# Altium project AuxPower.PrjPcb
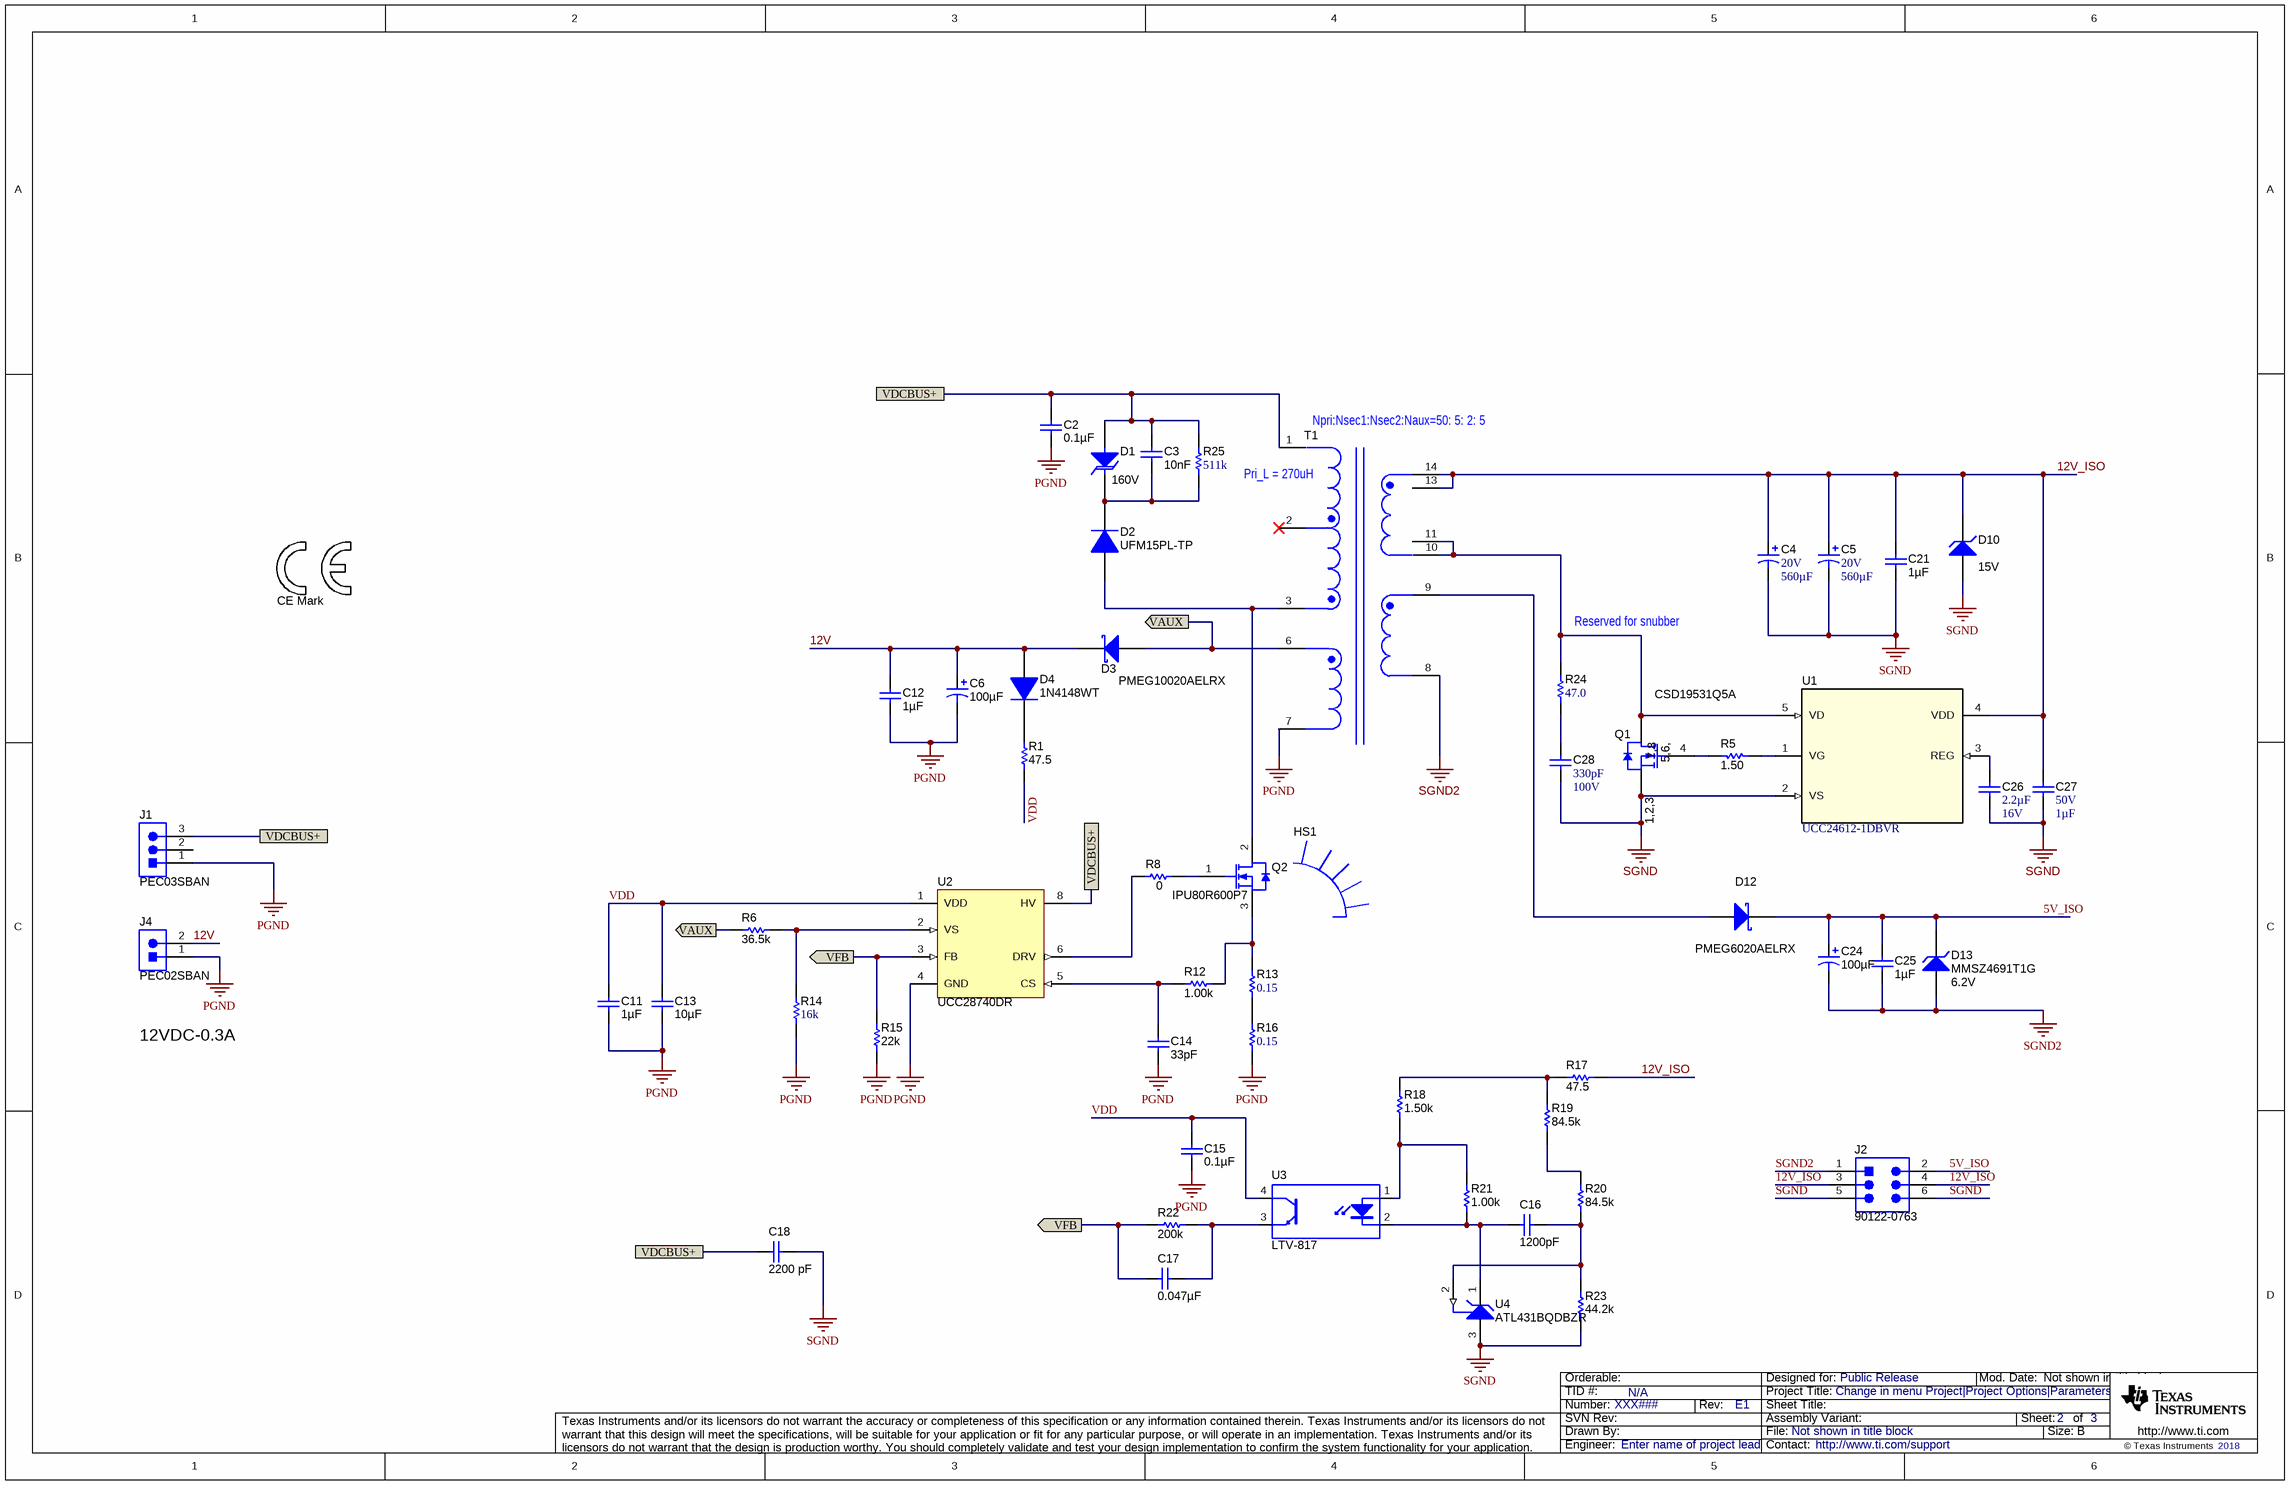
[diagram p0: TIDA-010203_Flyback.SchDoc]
CopyrightYear: 2018; PCB_Layout: Who did the Layout?; PCB_Rev: E1; PRJ_Customer: Public Release; PRJ_Engineer: Enter name of project lead; PRJ_Number: XXX###; PRJ_Title: Change in menu Project|Project Options|Parameters; SCH_Rev: E1; TechSupport: http://www.ti.com/support; TID: N/A
1 sheet, 56 parts. Net scope: flat (ports and power ports of the same name join across sheets).
Board file: TIDA-010203_Flyback.PcbDoc

## Sheet TIDA-010203_Flyback.SchDoc
size 431 x 279 mm; Date: Not shown in title block; ApprovedBy: Not shown in title block; CheckedBy: Not shown in title block; Author: Not shown in title block; CompanyName: Not shown in title block; Engineer: Not shown in title block; Organization: Not shown in title block; Address1: Not shown in title block; Address2: Not shown in title block; Address3: Not shown in title block; Address4: Not shown in title block; DocumentNumber: 1; Revision: Use project parameter SCH_Rev; SheetNumber: 2; SheetTotal: 3; PageSetup: Record=PageOptions¦CenterHorizontal=True¦CenterVertical=True¦PrintScale=1.00¦XCorrection=1.00¦YCorrection=1.00¦PrintKind=0¦BorderSize=5000000¦LeftOffset=0¦BottomOffset=0¦Orientation=2¦PaperLength=1000¦PaperWidth=1000¦Scale=100¦PaperSource=15¦PrintQuality=600¦MediaType=1¦DitherType=10¦PaperKind=Letter¦PrintScaleMode=1

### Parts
C2  ValueDisplayed: 0.1µF  [WCAP-FTXX_P10PL20_13x5x11]  (hidden comment: B32671P6104K)
C3  ValueDisplayed: 10nF  [0805_HV]  (hidden comment: C0805W103KBRAC7800)
C4  VDC_V: 20V  ValueDisplayed: 560µF  [SEPF_F13]  (hidden comment: 20SEPF560M)
C5  VDC_V: 20V  ValueDisplayed: 560µF  [SEPF_F13]  (hidden comment: 20SEPF560M)
C6  ValueDisplayed: 100µF  [CAPPR2-5x11]  (hidden comment: 25YXJ100M5X11)
C11  ValueDisplayed: 1µF  [0603]  (hidden comment: GRM188R61E105KA12D)
C12  ValueDisplayed: 1µF  [0603]  (hidden comment: C0603C105K3RACTU)
C13  ValueDisplayed: 10µF  [0603]  (hidden comment: GRM188R61E106MA73D)
C14  ValueDisplayed: 33pF  [0603]  (hidden comment: GRM1885C1H330JA01D)
C15  ValueDisplayed: 0.1µF  [0603]  (hidden comment: C1608X7R1H104K)
C16  ValueDisplayed: 1200pF  [0603]  (hidden comment: C1608C0G1H122J)
C17  ValueDisplayed: 0.047µF  [0603]  (hidden comment: C1608X7R1H473K)
C18  ValueDisplayed: 2200 pF  [C921_5500T_VertKink]  (hidden comment: DE1E3KX222MN4AP01F)
C21  ValueDisplayed: 1µF  [0603]  (hidden comment: C0603C105K3RACTU)
C24  ValueDisplayed: 100µF  [CAPPR2-5x11]  (hidden comment: 25YXJ100M5X11)
C25  ValueDisplayed: 1µF  [0603]  (hidden comment: C0603C105K3RACTU)
C26  Cap_F: 2.2µF  VDC_V: 16V  [0805_HV]  (hidden comment: GRM219R71C225KE15)
C27  VDC_V: 50V  Cap_F: 1µF  [0805_HV]  (hidden comment: GJ821BR71H105KA12L)
C28  Cap_F: 330pF  VDC_V: 100V  [0805_HV]  (hidden comment: 08051C331KAT2A)
D1  value 160V  [SMB]  (hidden comment: SMBJ160A)
D2  UFM15PL-TP  [SOD-123FL]
D3  PMEG10020AELRX  [SOD-123FL]
D4  1N4148WT  [Fairchild_SOD-523F]
D10  value 15V  [SOD-123]  (hidden comment: BZT52C15-7-F)
D12  PMEG6020AELRX  [SOD-123]
D13  MMSZ4691T1G  value 6.2V  [SOD-123]
HS1  ATS-PCBT1093  [HS_ATS-PCB1093]  (value not drawn)
J1  PEC03SBAN  [Sullins_PEC03SBAN]
J2  90122-0763  [Molex_90122-0763]
J4  PEC02SBAN  [Sullins_xxC02SBAN]
Logo8  CE Mark  [CE_Mark_5mm]  (no BOM)
Q1  CSD19531Q5A  [TRANS_NexFET_Q5A]
Q2  IPU80R600P7  [IPAK]
R1  ValueDisplayed: 47.5  [0805_HV]  (hidden comment: CRCW080547R5FKEA)
R5  ValueDisplayed: 1.50  [0603]  (hidden comment: CRCW06031R50FKEA)
R6  ValueDisplayed: 36.5k  [0603]  (hidden comment: CRCW060336K5FKEA)
R8  ValueDisplayed: 0  [0603]  (hidden comment: CRCW06030000Z0EA)
R12  ValueDisplayed: 1.00k  [0603]  (hidden comment: CRCW06031K00FKEA)
R13  ValueDisplayed: 0.15  [1206]  (hidden comment: ERJ-8BSFR15V)
R14  ValueDisplayed: 16k  [0603]  (hidden comment: 16k 0603)
R15  ValueDisplayed: 22k  [0603]  (hidden comment: CRCW060322K0JNEA)
R16  ValueDisplayed: 0.15  [1206]  (hidden comment: ERJ-8BSFR15V)
R17  ValueDisplayed: 47.5  [0603]  (hidden comment: CRCW060347R5FKEA)
R18  ValueDisplayed: 1.50k  [0603]  (hidden comment: CRCW06031K50FKEA)
R19  ValueDisplayed: 84.5k  [0603]  (hidden comment: CRCW060384K5FKEA)
R20  ValueDisplayed: 84.5k  [0603]  (hidden comment: CRCW060384K5FKEA)
R21  ValueDisplayed: 1.00k  [0603]  (hidden comment: CRCW06031K00FKEA)
R22  ValueDisplayed: 200k  [0603]  (hidden comment: CRCW0603200KFKEA)
R23  ValueDisplayed: 44.2k  [0603]  (hidden comment: CRCW060344K2FKEA)
R24  ValueDisplayed: 47.0  [0805_HV]  (hidden comment: MCU08050C4709FP500)
R25  ValueDisplayed: 511k  [1210]  (hidden comment: RC1210FR-07511KL)
T1  750344721  [WE_25/13/7]  (value not drawn)
U1  UCC24612-1DBVR  [DBV0005A_N]
U2  UCC28740DR  [D0007A_N]
U3  LTV-817  [DIP762W60P254L460H350Q4B]
U4  ATL431BQDBZR  [DBZ0003A_N]

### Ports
VAUX (out), VDCBUS+, VFB (out)

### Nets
PGND: C2.2 C6.2(-) C11.2 C12.2 C13.2 C14.2 C15.2 J1.1 J4.1 R14.1 R15.1 R16.1 T1.7 U2.4(GND)
SGND: C4.2(-) C5.2(-) C18.1 C21.2 C26.2 C27.2 C28.2 D10.2(A) J2.5 J2.6 Q1.1(S) Q1.2(S) Q1.3(S) R23.2 U1.2(VS) U4.3(ANODE)
SGND2: C24.2(-) C25.2 D13.2(A) J2.1 T1.8
5V_ISO: C24.1(+) C25.1 D12.1(K) D13.1(K) J2.2
12V: C6.1(+) C12.1 D3.1(K) D4.2(A) J4.2
12V_ISO: C4.1(+) C5.1(+) C21.1 C27.1 D10.1(K) J2.3 J2.4 R17.1 T1.13 T1.14 U1.4(VDD)
VAUX: D3.2(A) R6.2 T1.6 ; port VAUX
VDCBUS+: C2.1 C3.1 C18.2 D1.2(A) J1.3 R25.2 T1.1 U2.8(HV) ; port VDCBUS+
VDD: C11.1 C13.1 C15.1 R1.2 U2.1(VDD) U3.4(C)
VFB: C17.1 R15.2 R22.1 U2.3(FB) ; port VFB
NetC3_2: C3.2 D1.1(K) D2.1(K) R25.1
NetC14_1: C14.1 R12.1 U2.5(CS)
NetC16_1: C16.1 R20.1 R23.1 U4.2(REF)
NetC16_2: C16.2 R21.1 U3.2(K) U4.1(CATHODE)
NetC17_2: C17.2 R22.2 U3.3(E)
NetC26_1: C26.1 U1.3(REG)
NetC28_1: C28.1 R24.1
NetD2_2: D2.2(A) Q2.2(D) T1.3
NetD4_1: D4.1(K) R1.1
NetD12_2: D12.2(A) T1.9
NetQ1_4: Q1.4(G) R5.2
NetQ1_5: Q1.5(D) Q1.6(D) Q1.7(D) Q1.8(D) Q1.9(D) R24.2 T1.10 T1.11 U1.5(VD)
NetQ2_1: Q2.1(G) R8.2
NetQ2_3: Q2.3(S) R12.2 R13.2
NetR5_1: R5.1 U1.1(VG)
NetR6_1: R6.1 R14.2 U2.2(VS)
NetR8_1: R8.1 U2.6(DRV)
NetR13_1: R13.1 R16.2
NetR17_2: R17.2 R18.1 R19.2
NetR18_2: R18.2 R21.2 U3.1(A)
NetR19_1: R19.1 R20.2

Not connected (* = marked no-connect by the designer): J1 2; T1 2*

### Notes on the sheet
- (near T1) Npri:Nsec1:Nsec2:Naux=50: 5: 2: 5
- (near T1) Pri_L = 270uH
- (near R24) Reserved for snubber
- 12VDC-0.3A

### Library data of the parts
C2 = 890334023006: CAP, Film, 0.1 µF, 630 V, +/- 10%, TH; Manufacturer: TDK; Polarized: N; CompType: Capacitor; Value: 0.1uF; U/M: EA; Cap_F: 0.00000001; Tolerance_%: 10; Value1: Unknown; VDC_V: 630; Value2: 630V; TaMin_C: -40; TaMax_C: 105; Cap_Case: 13x5x11mm; AEC Category: Q200
C3 = C0805C103K1RACTU: 10000pF 630V Ceramic Capacitor X7R 0805; Manufacturer: Kemet; Polarized: N; Value: 0.01uF; U/M: EA; Tolerance_%: 10; Value1: 1.739 ohm; VDC_V: 630; TaMin_C: -55; TaMax_C: 125; Cap_Case: 0805; SizeArea_mm2: 2.5; SizeAreaWB_mm2: 6.75; SizeX_mm: 2; SizeY_mm: 1.25; SizeZ_mm: 1.45
C4 C5 = CMP-0081667-1: CAP, Aluminum Polymer, 560 µF, 20 V,+/- 20%, 0.012 ohm, TH; Manufacturer: Panasonic; IRMS_A: 5.4A; SizeAreaWB_mm2: 144; SizeArea_mm2: 100; AEC Qualified: N; AEC Category: Q200; Value: 560uF; TaMax_C: 105°C; SizeZ_mm: 13; Polarized: Y; TaMin_C: -55°C; SizeY_mm: 10; CompType: Capacitor; ESR_ohm: 0.012; Cap_Case: 10x13mm
C6 C24 = UVR1V100MDD1TA: CAP, AL, 100 µF, 25 V, +/- 20%, TH; Manufacturer: Rubycon; Polarized: Y; CompType: Capacitor; Value: 100uF; U/M: EA; Cap_F: 0.00001; Tolerance_%: 20; Value1: Unknown; VDC_V: 25; Value2: 25V; TaMin_C: -40; TaMax_C: 85; Cap_Case: 5x11; AEC Category: Q200; AEC Qualified: N
C11 = GRM188R61E105KA12D: CAP, CERM, 1 µF, 25 V, +/- 10%, X5R, 0603; Manufacturer: MuRata; Polarized: N; CompType: Capacitor; Value: 1uF; U/M: EA; Cap_F: 0.000001; Tolerance_%: 10; Value1: Unknown; VDC_V: 25; Value2: 25V; TaMin_C: -55; TaMax_C: 85; SizeArea_mm2: 1.28; SizeAreaWB_mm2: 4.68; SizeX_mm: 1.6; SizeY_mm: 0.8; SizeZ_mm: 1; AEC Category: Q200
C12 C21 C25 = C0603C105K8PACTU: CAP CER 1UF 25V X7R 0603; Manufacturer: Kemet; Polarized: N; CompType: Capacitor; U/M: EA; Cap_F: 0.000001; Tolerance_%: 10; Value1: Unknown; Value2: 10V; TempCo: X5R; TaMin_C: -55; TaMax_C: 85; AEC Category: Q200
C13 = GRM188R61E106MA73D: CAP, CERM, 10 µF, 25 V, +/- 20%, X5R, 0603; Manufacturer: MuRata; Polarized: N; CompType: Capacitor; Value: 10uF; U/M: EA; Cap_F: 0.00001; Tolerance_%: 20; Value1: Unknown; VDC_V: 25; Value2: 25V; TaMin_C: -55; TaMax_C: 85; SizeArea_mm2: 1.28; SizeAreaWB_mm2: 4.68; SizeX_mm: 1.6; SizeY_mm: 0.8; SizeZ_mm: 1; AEC Category: Q200
C14 = GRM1885C1H330JA01D: CAP, CERM, 33 pF, 50 V, +/- 5%, C0G/NP0, 0603; Manufacturer: MuRata; Polarized: N; CompType: Capacitor; Value: 33pF; U/M: EA; Cap_F: 0.000000000033; Tolerance_%: 5; Value1: Unknown; VDC_V: 50; Value2: 50V; TaMin_C: -55; TaMax_C: 125; AEC Category: Q200
C15 = C1608X7R1H104K: CAP, CERM, 0.1 µF, 50 V, +/- 10%, X7R, 0603; Manufacturer: TDK; Polarized: N; CompType: Capacitor; Value: 0.1uF; U/M: EA; Cap_F: 0.0000001; Tolerance_%: 10; ESR_ohm: 0.017; Value1: 0.017 ohm; VDC_V: 50; Value2: 50V; TaMin_C: -55; TaMax_C: 125
C16 = C1608C0G1H122J: CAP, CERM, 1200 pF, 50 V, +/- 5%, C0G/NP0, 0603; Manufacturer: TDK; Polarized: N; CompType: Capacitor; Value: 1200pF; U/M: EA; Cap_F: 0.0000000012; Tolerance_%: 5; Value1: Unknown; VDC_V: 50; Value2: 50V; TaMin_C: -55; TaMax_C: 125; AEC Category: Q200
C17 = C1608X7R1H473K: CAP, CERM, 0.047 µF, 50 V, +/- 10%, X7R, 0603; Manufacturer: TDK; Polarized: N; CompType: Capacitor; Value: 0.047uF; U/M: EA; Cap_F: 0.000000047; Tolerance_%: 10; ESR_ohm: 0.0234; Value1: 0.0234 ohm; VDC_V: 50; Value2: 50V; TaMin_C: -55; TaMax_C: 125
C18 = C921U222MUVDBA7317: CAP, CERM, 2.2 µF, 250 V, +/- 20%, Y5V, Cap 9x13mm; Manufacturer: Kemet; Polarized: N; CompType: Capacitor; Value: 2200 pF; U/M: EA; Tolerance_%: 20; Value1: Unknown; VDC_V: 250; Value2: 300 V; TaMin_C: -25; TaMax_C: 125; AEC Category: Q200
C26 = CMP-0008211-2: CAP, CERM, 2.2 uF, 16 V, +/- 10%, X7R, 0805; Manufacturer: MuRata; TaMin_C: -55°C; Polarized: N; SizeAreaWB_mm2: 6.75; Value1: Unknown; U/M: EA; Value: 2.2uF; TaMax_C: 125°C; SizeZ_mm: 1.45; SizeX_mm: 2; SizeY_mm: 1.25; Cap_Case: 0805; SizeArea_mm2: 2.5; AEC Category: Q200
C27 = CMP-0750127-1: CAP, CERM, 1 µF, 50 V,+/- 10%, X7R, 0805; Manufacturer: MuRata; U/M: EA; SizeArea_mm2: 2.5; SizeAreaWB_mm2: 6.75; Cap_Case: 0805; Polarized: N; SizeZ_mm: 1.45; SizeX_mm: 2; TaMin_C: -55°C; Value: 1uF; TaMax_C: 125°C; SizeY_mm: 1.25; AEC Category: Q200
C28 = CMP-0007553-2: CAP, CERM, 330 pF, 100 V, +/- 10%, X7R, 0805; Manufacturer: AVX; TaMin_C: -55°C; ESR_ohm: 5.63d; Polarized: N; SizeAreaWB_mm2: 6.75; Value1: 0.563 ohm; U/M: EA; Value: 330pF; TaMax_C: 125°C; SizeZ_mm: 1.45; SizeX_mm: 2; SizeY_mm: 1.25; Cap_Case: 0805; SizeArea_mm2: 2.5; AEC Category: Q200
D1 = SMBJ160A-13-F: TVS DIODE 160VWM 259VC SMB; Manufacturer: Fairchild Semiconductor; U/M: EA; Power_W: 5; Vr_V: 160; Value1: 5W; AEC Category: Q101
D2 = CMP-0029148-2: Diode, Ultrafast, 600 V, 1 A, SOD-123FL; Manufacturer: Micro Commercial Components; SizeY_mm: 1.65; Value: 600V; Io_A: 1A; Green_Lifecycle: Not Set; Green_REACh: Incomplete; SizeX_mm: 3.6; SizeAreaWB_mm2: 12.19; SizeArea_mm2: 5.94; AEC Qualified: N; Value2: 1.7V; SizeZ_mm: 0.98; AEC Category: Q101; TJmax_C: 150°C
D3 = MBR1H100SFT3G: DIODE SCHOTTKY 100V 2A SOD2123; Manufacturer: NXP Semiconductors; U/M: EA; Vf_V: 0.85; Value: 150V; Value1: 1A; Value2: 0.85V; Io_A: 1; Vr_V: 200; AEC Category: Q101
D4 = 1N4148WT: Diode, Switching, 75 V, 0.3 A, SOD-523F; Manufacturer: Fairchild Semiconductor; U/M: EA; Value: 75V; Value1: 0.3A; Io_A: 0.3; Vr_V: 75; TJmax_C: 150; AEC Category: Q101
D10 D13 = BZT52C15-7-F: Diode, Zener, 15 V, 370 mW, AEC-Q101, SOD-123; Manufacturer: Diodes Inc.; SymbolCreator: a0412235; U/M: EA; Power_W: 0.37; Vz_V: 15; Value1: 0.37W; RJA_CperW: 338; AEC Category: Q101; AEC Qualified: Y
D12 = MBR1H100SFT3G: DIODE SCHOTTKY 60V 2A SOD2123; Manufacturer: NXP Semiconductors; U/M: EA; Vf_V: 0.85; Value: 150V; Value1: 1A; Value2: 0.85V; Io_A: 1; Vr_V: 200; AEC Category: Q101
HS1 = 150CN-02000-A-200: Heat Sink TO-220 Copper Board Level, Vertical; Manufacturer: Advanced Thermal Solutions Inc.; SymbolCreator: a0412235
J1 = CMP-0054704-1: Header, 100mil, 3x1, Tin, R/A, TH; Manufacturer: Sullins Connector Solutions; CNHeader: FALSE; Current_A: 3A; Green_Lifecycle: Not Set; Shrouded: N; Gender: Male; Green_REACh: Incomplete; Voltage_V: 1.8kV; Row_Count: 1; Pitch_mm: 2.54; Cert_UL: Y
J2 = CMP-0077741-2: Header, 2.54mm, 3x2, Gold, R/A, TH; Manufacturer: Molex; Pitch_mm: 2.54; Gender: Male; Cert_UL: Y; Current_A: 3A; Voltage_V: 350V; Shrouded: N; Row_Count: 2
J4 = PEC02SBAN: Header, 2.54 mm, 2x1, Tin, R/A, TH; Manufacturer: Sullins Connector Solutions; SymbolCreator: a0412235; Pitch_mm: 2.54; Gender: Male; Shrouded: N; Row_Count: 1; Current_A: 3; Voltage_V: 1800; Cert_UL: Y
Logo8 = CMP-0074844-1: SymbolCreator: a0412235
Q1 = CSD19531Q5A: MOSFET, N-CH, 100 V, 16 A, SON 5x6mm; Manufacturer: Texas Instruments; Alternate Manufacturer: None; U/M: EA; ChType: N; Value: 100V; VdsMax_V: 100; Value1: ? ohm; Value2: 36 nC; QgTyp_nC: 36; Vgs_V: 20; IdsMax_A: 16; AEC Category: Q101
Q2 = IPU60R2K0C6BKMA1: MOSFET, N-CH, 650 V, 2.4 A, IPAK; Manufacturer: Infineon Technologies; Alternate Manufacturer: None; U/M: EA; ChType: N; Value: 800V; VdsMax_V: 650; Value1: ? ohm; Value2: 6.7 nC; QgTyp_nC: 6.7; Vgs_V: 20; IdsMax_A: 2.4; AEC Category: Q101
R1 = CRCW080547R5FKEA: RES, 47.5, 1%, 0.125 W, 0805; Manufacturer: Vishay-Dale; CompType: Resistor; Value: 47.5; Value_Code: 47R5; Tolerance_%: 1; Power_W: 0.125; Value2: 0.125W; VDC_V: 150; TempCo: 100 ppm/C; EIA_Code: E96; U/M: EA
R5 = CRCW06031R50FKEA: RES, 1.50, 1%, 0.1 W, 0603; Manufacturer: Vishay-Dale; CompType: Resistor; Value: 1.50; Res_ohm: 1.5; Value_Code: 1R50; Tolerance_%: 1; Power_W: 0.1; Value2: 0.1W; VDC_V: 75; TempCo: 100 ppm/C; EIA_Code: E96; U/M: EA
R6 = CRCW060346K4FKEA: RES, 36.5 k, 1%, 0.1 W, 0603; Manufacturer: Vishay-Dale; CompType: Resistor; Value: 36.5k; Res_ohm: 46400; Tolerance_%: 1; Power_W: 0.1; Value2: 0.1W; VDC_V: 75; TempCo: 100 ppm/C; EIA_Code: E96; U/M: EA; AEC Category: Q200
R8 = CRCW06030000Z0EA: RES, 0, 5%, 0.1 W, 0603; Manufacturer: Vishay-Dale; CompType: Resistor; Value: 0; Value_Code: 0000; Tolerance_%: 5; Power_W: 0.1; Value2: 0.1W; VDC_V: 75; TempCo: 200 ppm/C; EIA_Code: E24; U/M: EA; AEC Category: Q200
R12 = CRCW06031K87FKEA: RES, 1.00k, 1%, 0.1 W, 0603; Manufacturer: Vishay-Dale; CompType: Resistor; Value: 1k; Res_ohm: 1870; Tolerance_%: 1; Power_W: 0.1; Value2: 0.1W; VDC_V: 75; TempCo: 100 ppm/C; EIA_Code: E96; U/M: EA; AEC Category: Q200
R13 = CMP-0017277-2: RES, 0.15, 1%, 0.5 W, 1206; Manufacturer: Panasonic; Power_W: 500mW; TempCo: 250 ppm/C; Value_Code: R150; U/M: EA; Value: 0.15; EIA_Code: E96; Res_ohm: 1.5d; SizeX_mm: 3.2; SizeY_mm: 1.6; SizeZ_mm: 1.35; Value2: 0.5W; SizeArea_mm2: 5.12; AEC Qualified: N; AEC Category: Q200
R14 = CMP-0025723-4: RES, 16 k, 5%, 0.1 W, AEC-Q200 Grade 0, 0603; Manufacturer: Vishay-Dale; PartNumber: CRCW060316K0JNEA; Power_W: 100mW; TempCo: 200 ppm/C; EIA_Code: E24; SizeX_mm: 1.6; SizeY_mm: 0.8; SizeZ_mm: 1; Value2: 0.1W; SizeArea_mm2: 1.28; AEC Qualified: Y; VDC_V: 75V; AEC Category: Q200; AEC Grade: 0
R15 = CRCW060322K0JNEA: RES, 22 k, 5%, 0.1 W, 0603; Manufacturer: Vishay-Dale; CompType: Resistor; Value: 22k; Res_ohm: 22000; Value_Code: 22k0; Tolerance_%: 5; Power_W: 0.1; Value2: 0.1W; VDC_V: 75; TempCo: 200 ppm/C; EIA_Code: E24; U/M: EA; AEC Category: Q200
R16 = CMP-0017277-2: RES, 0.15, 1%, 0.5 W, 1206; Manufacturer: Panasonic; Power_W: 500mW; TempCo: 250 ppm/C; Value_Code: R150; U/M: EA; Value: 0.15; EIA_Code: E96; Res_ohm: 1.5d; SizeX_mm: 3.2; SizeY_mm: 1.6; SizeZ_mm: 1.35; Value2: 0.5W; SizeArea_mm2: 5.12; CompType: Resistor; AEC Qualified: N; AEC Category: Q200
R17 = CRCW060347R5FKEA: RES, 47.5, 1%, 0.1 W, 0603; Manufacturer: Vishay-Dale; CompType: Resistor; Value: 47.5; Value_Code: 47R5; Tolerance_%: 1; Power_W: 0.1; Value2: 0.1W; VDC_V: 75; TempCo: 100 ppm/C; EIA_Code: E96; U/M: EA
R18 = CRCW06031K50FKEA: RES, 1.50 k, 1%, 0.1 W, 0603; Manufacturer: Vishay-Dale; CompType: Resistor; Value: 1.50k; Res_ohm: 1500; Value_Code: 1k50; Tolerance_%: 1; Power_W: 0.1; Value2: 0.1W; VDC_V: 75; TempCo: 100 ppm/C; EIA_Code: E96; U/M: EA
R19 R20 = CRCW060384K5FKEA: RES, 84.5 k, 1%, 0.1 W, 0603; Manufacturer: Vishay-Dale; CompType: Resistor; Value: 84.5k; Res_ohm: 84500; Value_Code: 84k5; Tolerance_%: 1; Power_W: 0.1; Value2: 0.1W; VDC_V: 75; TempCo: 100 ppm/C; SizeArea_mm2: 1.28; SizeX_mm: 1.6; SizeY_mm: 0.8; EIA_Code: E96; U/M: EA; AEC Category: Q200
R21 = CRCW06031K00FKEA: RES, 1.00 k, 1%, 0.1 W, 0603; Manufacturer: Vishay-Dale; CompType: Resistor; Value: 1.00k; Res_ohm: 1000; Value_Code: 1k00; Tolerance_%: 1; Power_W: 0.1; Value2: 0.1W; VDC_V: 75; TempCo: 100 ppm/C; EIA_Code: E96; U/M: EA
R22 = CRCW0603200KFKEA: RES, 200 k, 1%, 0.1 W, 0603; Manufacturer: Vishay-Dale; CompType: Resistor; Value: 200k; Res_ohm: 200000; Tolerance_%: 1; Power_W: 0.1; Value2: 0.1W; VDC_V: 75; TempCo: 100 ppm/C; EIA_Code: E96; U/M: EA; AEC Category: Q200
R23 = CRCW060344K2FKEA: RES, 44.2 k, 1%, 0.1 W, 0603; Manufacturer: Vishay-Dale; CompType: Resistor; Value: 44.2k; Res_ohm: 44200; Value_Code: 44k2; Tolerance_%: 1; Power_W: 0.1; Value2: 0.1W; VDC_V: 75; TempCo: 100 ppm/C; EIA_Code: E96; U/M: EA
R24 = CMP-0021861-2: RES, 47.0, 1%, 0.2 W, 0805; Manufacturer: Vishay/Beyschlag; Power_W: 200mW; TempCo: 50 ppm/C; Value_Code: 47R0; U/M: EA; Value: 47.0; Res_ohm: 47; SizeX_mm: 2; SizeY_mm: 1.25; SizeZ_mm: 1.45; Value2: 0.2W; SizeArea_mm2: 2.5; AEC Qualified: N; AEC Category: Q200
R25 = CMP-0083237-1: RES, 511 k, 1%, 0.5 W, 1210; Manufacturer: Yageo; Power_W: 500mW; TempCo: 100 ppm/C; SizeAreaWB_mm2: 14.7; Value: 511k; EIA_Code: E96; SizeX_mm: 3.2; SizeY_mm: 2.5; SizeZ_mm: 1.35; Value2: 0.5W; SizeArea_mm2: 8; AEC Qualified: N; VDC_V: 200V; AEC Category: Q200
T1 = WE_trans: flyback transformer
U1 = UCC24612-1DBVR: Imported; Manufacturer: Texas Instruments
U2 = UCC28740DR: Constant-Voltage, Constant-Current Flyback Controller Using Opto-Coupler Feedback, D0007A; Manufacturer: Texas Instruments; SymbolCreator: a0412235; CompType: IC; U/M: EA
U3 = LTV-817: Optocoupler, 5 kV, 50-600% CTR, TH-4; Manufacturer: Lite-On; U/M: EA; CTR_Min: 50% @ 5mA; CTR_Max: 600% @ 5mA; Voltage_Isolation_Vrms: 5000; tr_typ: 4us; tf_typ: 3us
U4 = ATL431BQDBZR: 2.5V Low Iq Adjustable Precision Shunt Regulator, DBZ0003A; Alternate PartNumber: ATL431BQDBZT; Manufacturer: Texas Instruments; SymbolCreator: a0412235; CompType: IC; U/M: EA

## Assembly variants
001: not fitted FID1 FID2 FID3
